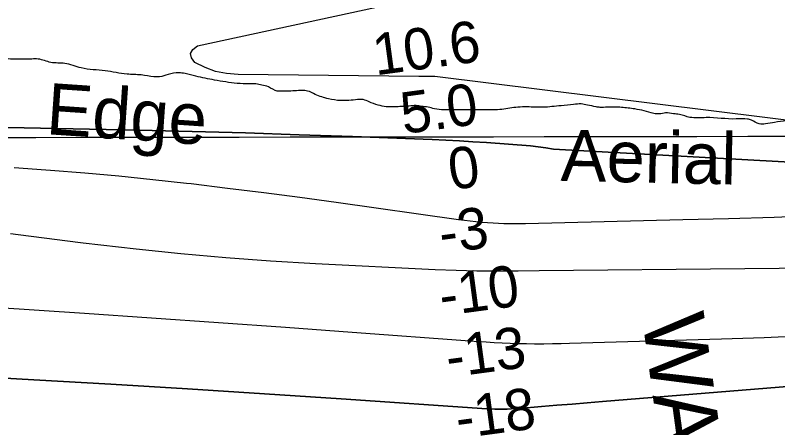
# Model space of a CAD drawing. Extents: x 3329297 to 3367176, y 649250 to 674653.
# Drawn here: x 3335278 to 3336510, y 660227 to 660894 of the extents above; entities that cross this region are included whole.
import ezdxf

# ---------------------------------------------------------------- set-up
doc = ezdxf.new("R2010")
doc.units = 0
for name, color, linetype in [('V-CHAN-NAID', 7, 'Continuous'), ('V-GRID-MAJR', 7, 'Continuous'), ('V-RIVR-EDGE', 7, 'Continuous'), ('V-RIVR-IDEN', 7, 'Continuous'), ('V-RIVR-RANG', 7, 'Continuous'), ('V-TOPO-DPTH', 7, 'Continuous'), ('V-TOPO-MINR', 7, 'Continuous'), ('V-TOPO-WATR', 7, 'Continuous')]:
    doc.layers.add(name, color=color, linetype=linetype)

msp = doc.modelspace()

# ---------------------------------------------------------------- linework, layer by layer
at = {"layer": 'V-GRID-MAJR'}
msp.add_spline([(3333421.13, 660693.428), (3338679.904, 660701.46), (3343938.678, 660710.256), (3349197.451, 660719.817), (3354456.222, 660730.142), (3359714.992, 660741.233), (3364973.7600000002, 660753.089), (3364973.761, 660753.089)], degree=3, dxfattribs=at)
at = {"layer": 'V-RIVR-EDGE'}
msp.add_spline([(3338937.398556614, 661038.9798826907), (3338922.836359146, 661016.6337518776), (3338913.2879107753, 661010.4401016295), (3338909.5534775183, 661008.7913995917), (3338900.440008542, 661010.8863548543), (3338872.2716634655, 661017.5877519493), (3338863.9820330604, 661017.6082498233), (3338847.3945731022, 661014.3333934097), (3338836.5955059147, 661005.2414472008), (3338822.87969468, 660989.9394524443), (3338803.3590923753, 660973.8228431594), (3338792.145543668, 660964.7319218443), (3338778.457404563, 660960.6209281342), (3338766.4374404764, 660960.6506500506), (3338750.670744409, 660954.0578916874), (3338739.877826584, 660947.4528346), (3338731.1439927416, 660935.4543932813), (3338722.8154163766, 660919.7245933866), (3338710.758556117, 660904.8329805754), (3338699.5429576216, 660894.91309622), (3338689.159396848, 660886.2346066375), (3338668.4199474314, 660880.0686285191), (3338645.5978414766, 660869.762959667), (3338618.61452202, 660852.8358354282), (3338593.279904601, 660832.1742779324), (3338577.0946274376, 660823.924618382), (3338559.2524490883, 660816.0935399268), (3338550.1348805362, 660816.5305691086), (3338538.9469541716, 660817.8016857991), (3338524.0461173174, 660826.1282123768), (3338507.906960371, 660836.5302212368), (3338499.6306535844, 660841.9389788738), (3338492.6111149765, 660852.7329215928), (3338476.8915640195, 660865.2063131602), (3338462.809441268, 660869.3859747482), (3338450.374995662, 660869.416721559), (3338418.4609434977, 660869.9101198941), (3338390.2649262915, 660865.4205159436), (3338365.786944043, 660855.9479097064), (3338351.2677921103, 660851.010002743), (3338337.587852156, 660850.2148611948), (3338306.0964806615, 660854.0230867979), (3338289.5213194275, 660855.7220086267), (3338264.2461458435, 660859.1003793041), (3338251.4013182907, 660860.79007709), (3338243.526169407, 660860.8095500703), (3338233.9879699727, 660858.7607150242), (3338222.78671999, 660854.6435719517), (3338211.5752210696, 660846.381613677), (3338201.1783366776, 660832.314864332), (3338189.927891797, 660808.3026082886), (3338183.261341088, 660794.2266349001), (3338178.666173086, 660779.7310555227), (3338170.7705263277, 660771.4608980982), (3338158.317632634, 660764.0309775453), (3338133.0158118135, 660756.632828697), (3338097.3509280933, 660748.8458206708), (3338043.0333510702, 660740.6904513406), (3337961.7744752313, 660732.6017001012), (3337939.4016971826, 660736.3873780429), (3337925.7412302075, 660743.4673853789), (3337919.956937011, 660750.9424012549), (3337915.424287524, 660761.7301946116), (3337898.1175281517, 660802.8069106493), (3337891.911579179, 660807.3815807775), (3337869.5377762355, 660810.7527771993), (3337845.49989785, 660811.6411840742), (3337821.0444632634, 660811.2871712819), (3337801.5587073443, 660809.2629336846), (3337782.0637273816, 660803.5083624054), (3337764.216424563, 660793.604876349), (3337739.713844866, 660774.1847136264), (3337721.0140064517, 660754.7502023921), (3337697.738473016, 660728.6952606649), (3337679.4746388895, 660717.963836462), (3337644.2119379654, 660705.2020252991), (3337603.984682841, 660696.182846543), (3337565.4245778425, 660690.8899018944), (3337510.301610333, 660692.2696573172), (3337469.272039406, 660694.0290478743), (3337430.314876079, 660695.7833139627), (3337388.874923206, 660699.2016554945), (3337358.619822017, 660700.105435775), (3337304.319668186, 660698.996252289), (3337262.866391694, 660697.026334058), (3337234.678573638, 660695.8525822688), (3337203.591434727, 660695.5149677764), (3337186.597692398, 660695.5569884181), (3337167.5233433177, 660692.2882813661), (3337153.831104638, 660686.5193615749), (3337137.251843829, 660686.5603573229), (3337124.4029167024, 660686.5921290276), (3337108.235062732, 660685.3886553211), (3337095.376911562, 660681.690093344), (3337086.671774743, 660681.2971345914), (3337075.483848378, 660682.568251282), (3337053.112095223, 660686.7684107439), (3337038.6083166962, 660688.0477265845), (3337026.9997594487, 660686.8329790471), (3337008.7625725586, 660686.87807437), (3337000.0574357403, 660686.4851156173), (3336990.1139788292, 660688.1676391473), (3336974.372905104, 660691.9369187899), (3336966.9173622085, 660694.0277744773), (3336960.7001394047, 660694.0431478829), (3336948.27184316, 660696.5607838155), (3336935.0053598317, 660695.350135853), (3336912.630531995, 660698.3068507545), (3336901.038373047, 660703.723807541), (3336890.6753101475, 660703.3349483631), (3336866.220900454, 660703.3954170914), (3336823.121996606, 660706.403376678), (3336801.991638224, 660709.7714984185), (3336787.48580991, 660710.2218512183), (3336751.422842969, 660709.0675724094), (3336727.3849645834, 660709.9559792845), (3336706.2556310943, 660713.7385825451), (3336691.7600517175, 660718.3337505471), (3336674.7652844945, 660717.9612896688), (3336645.3247978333, 660713.0602788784), (3336625.8451912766, 660713.5229304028), (3336606.791340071, 660718.5438537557), (3336592.2875615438, 660719.823169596), (3336570.7345224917, 660719.8764640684), (3336558.7135335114, 660719.4917044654), (3336550.4300524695, 660721.9990914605), (3336541.7310650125, 660724.0930218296), (3336533.855916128, 660724.1124948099), (3336524.320791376, 660723.3071043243), (3336504.8329856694, 660720.4539036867), (3336490.319983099, 660718.0028858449), (3336479.957945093, 660718.0285081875), (3336467.5388728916, 660724.2764778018), (3336461.3257496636, 660725.9497772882), (3336442.6740812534, 660725.9958975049), (3336394.1848678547, 660728.1882176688), (3336368.0735569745, 660728.667267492), (3336351.091088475, 660733.2685848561), (3336341.561088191, 660734.5356019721), (3336328.715235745, 660735.8108182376), (3336318.763579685, 660734.1774896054), (3336309.647036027, 660735.0290003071), (3336293.9069871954, 660739.2127614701), (3336278.992826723, 660742.1510282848), (3336257.4459370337, 660744.6912118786), (3336234.235996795, 660745.163087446), (3336223.043970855, 660744.7762780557), (3336216.4143163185, 660745.6216393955), (3336202.3291188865, 660748.557856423), (3336192.385661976, 660750.2403799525), (3336179.949166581, 660749.442163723), (3336160.0489291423, 660747.4189510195), (3336130.200110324, 660745.005854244), (3336105.332244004, 660745.4818293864), (3336089.995402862, 660745.1052689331), (3336064.288324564, 660741.4384786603), (3336035.687049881, 660740.6802332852), (3335999.6271576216, 660740.7693990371), (3335970.198969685, 660740.8421664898), (3335955.2817345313, 660742.5369887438), (3335944.925845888, 660745.0495002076), (3335934.1524010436, 660746.3195920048), (3335925.4513637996, 660747.584559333), (3335914.2583129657, 660746.7832684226), (3335899.3349284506, 660745.9912015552), (3335888.1429025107, 660745.604392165), (3335877.366382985, 660745.631039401), (3335864.110148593, 660748.5652066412), (3335849.6155941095, 660753.5748561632), (3335840.091743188, 660757.3287624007), (3335830.9731497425, 660757.351310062), (3335803.1987883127, 660755.7620518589), (3335783.725331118, 660758.7115925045), (3335762.6041967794, 660765.810047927), (3335750.183074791, 660771.2290545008), (3335741.4810126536, 660772.0795403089), (3335717.0235282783, 660770.8965644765), (3335708.319416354, 660770.9180872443), (3335701.27323051, 660770.935510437), (3335686.7838004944, 660778.0175675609), (3335676.4289367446, 660780.9445605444), (3335666.485479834, 660782.6270840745), (3335656.123441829, 660782.6527064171), (3335636.230378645, 660783.5308643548), (3335599.769328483, 660789.0093147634), (3335569.527550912, 660795.3013548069), (3335552.129575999, 660799.4892155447), (3335542.1850941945, 660800.7572575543), (3335524.769696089, 660797.8989324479), (3335511.0825818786, 660794.2024202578), (3335501.9639884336, 660794.2249679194), (3335481.2470866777, 660797.177583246), (3335458.453677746, 660798.47739696), (3335422.8215906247, 660803.9537975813), (3335384.2860830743, 660808.6084094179), (3335357.7766889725, 660815.7201884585), (3335335.3987864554, 660817.4334587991), (3335314.6880340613, 660822.8729632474), (3335304.7404775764, 660822.8975606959), (3335277.3836723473, 660822.5507221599), (3335247.549202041, 660825.940366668), (3335233.878486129, 660828.8755588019), (3335221.026484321, 660827.6638859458), (3335203.625434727, 660830.6083021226), (3335183.743645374, 660836.0457567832), (3335171.31534913, 660838.5633927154), (3335154.737113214, 660839.018869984), (3335125.2966265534, 660834.1178591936), (3335103.735388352, 660830.8553015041), (3335075.1402630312, 660832.5839452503), (3335059.384840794, 660830.5504836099), (3335036.1718258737, 660829.7789146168), (3335026.228368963, 660831.4614381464), (3335016.7004184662, 660833.5574183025), (3334988.130915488, 660845.6481000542), (3334968.2460514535, 660849.8421101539), (3334947.1064690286, 660849.4798982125), (3334935.092654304, 660851.9965092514), (3334919.773236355, 660858.6661346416), (3334910.6618171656, 660861.590052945), (3334896.5776446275, 660864.9407514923), (3334875.443186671, 660866.6509471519), (3334846.8429368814, 660866.3071832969), (3334814.088647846, 660862.243334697), (3334799.57667017, 660860.2067983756), (3334786.3122366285, 660859.8251134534), (3334763.9394585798, 660863.6107913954), (3334750.6760499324, 660863.6435879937), (3334729.9529988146, 660864.109314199), (3334716.282282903, 660867.0445063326), (3334687.694331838, 660871.6745207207), (3334669.46329431, 660874.2065051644), (3334645.8491214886, 660878.8242208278), (3334635.4901581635, 660880.0932877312), (3334625.5446514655, 660880.9468482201), (3334596.949526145, 660882.6754919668), (3334567.1037820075, 660881.5058397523), (3334557.5717319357, 660881.9438938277), (3334545.9723987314, 660884.4594799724), (3334521.960142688, 660895.7099248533), (3334508.2955761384, 660901.1320061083), (3334490.067613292, 660904.907435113), (3334462.7077333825, 660903.3171520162), (3334451.5157074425, 660902.9303426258), (3334433.69505186, 660903.8033760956), (3334404.697743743, 660910.5068229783), (3334381.0886953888, 660917.1969462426), (3334364.9331401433, 660920.9672507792), (3334352.917275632, 660922.6548987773), (3334336.75454613, 660923.5238326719), (3334316.437777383, 660920.6726818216), (3334296.5477888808, 660922.7942843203), (3334284.541148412, 660928.2122660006), (3334260.9239009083, 660931.5865371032), (3334243.938357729, 660934.9444099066), (3334228.60254148, 660934.9823309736), (3334209.532291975, 660933.3715500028), (3334195.436845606, 660932.162951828), (3334181.763055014, 660933.854699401), (3334171.4030667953, 660934.709284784), (3334166.848894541, 660936.7929662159), (3334153.5844610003, 660936.4112812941), (3334133.268717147, 660933.9746119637), (3334121.2549024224, 660936.4912230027), (3334114.214865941, 660938.9955353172), (3334098.0582858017, 660942.3513583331), (3334086.040371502, 660943.2100432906), (3334069.0538034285, 660946.1534345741), (3334054.956307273, 660944.1158733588), (3334034.2312063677, 660943.752636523), (3334004.815317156, 660948.7991822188), (3333961.735886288, 660959.6822906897), (3333930.2486143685, 660965.1484423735), (3333912.4402575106, 660970.995254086), (3333902.508074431, 660977.2370743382), (3333891.3344965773, 660984.3109323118), (3333867.3160911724, 660993.0744880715), (3333818.846350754, 661003.1419571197), (3333763.753105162, 661016.5416766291), (3333734.3484897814, 661026.147519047), (3333691.6855902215, 661037.8585656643), (3333658.539367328, 661042.914335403), (3333635.331476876, 661044.215174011), (3333621.6494871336, 661042.591069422), (3333588.8951980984, 661038.5272208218), (3333566.0946149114, 661036.9256638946), (3333542.057761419, 661038.2285522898), (3333498.9629571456, 661042.8944379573), (3333465.8218587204, 661050.0226152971), (3333420.687729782, 661060.1318435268)], degree=3, dxfattribs=at)
at = {"layer": 'V-TOPO-DPTH'}
for points in [[(3335026.822229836, 660717.3138612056), (3335477.2484609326, 660707.7378849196), (3335563.638599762, 660705.6865478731), (3335650.020286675, 660703.3491414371), (3335736.389295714, 660700.5826309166), (3335822.749852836, 660697.5300510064), (3335951.5333759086, 660692.6576272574), (3335973.4890870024, 660691.7065191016), (3335995.435807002, 660690.5952209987), (3336017.36904036, 660689.2436379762), (3336039.2932826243, 660687.7318650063), (3336110.386908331, 660682.438324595), (3336122.9389972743, 660681.174766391), (3336135.4211949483, 660679.4805481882), (3336147.7985557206, 660677.1403399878), (3336775.750459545, 660642.6610791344)], [(3336775.750459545, 660642.6610791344), (3336147.7985557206, 660677.1403399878), (3336135.4211949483, 660679.4805481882), (3336122.9389972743, 660681.174766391), (3336110.386908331, 660682.438324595), (3336039.2932826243, 660687.7318650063), (3336017.36904036, 660689.2436379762), (3335995.435807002, 660690.5952209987), (3335973.4890870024, 660691.7065191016), (3335951.5333759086, 660692.6576272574), (3335822.749852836, 660697.5300510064), (3335736.389295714, 660700.5826309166), (3335650.020286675, 660703.3491414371), (3335563.638599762, 660705.6865478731), (3335477.2484609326, 660707.7378849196), (3335026.822229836, 660717.3138612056)], [(3336788.996719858, 660486.9109705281), (3336124.140254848, 660480.7398634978), (3336090.6047070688, 660480.040770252), (3336057.069502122, 660479.8302104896), (3336023.541559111, 660480.0576026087), (3335990.024509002, 660480.9419225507), (3335956.514720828, 660482.2641943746), (3335762.9419088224, 660491.8030816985), (3335690.339409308, 660496.0912212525), (3335617.8141429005, 660501.3219623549), (3335545.404726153, 660507.9666057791), (3335473.072542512, 660515.5538507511), (3335387.3409469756, 660525.3931573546), (3335357.947108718, 660528.8822601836), (3335328.5726967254, 660532.523257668), (3335299.227424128, 660536.392097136), (3335269.901577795, 660540.4128312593)], [(3336788.996719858, 660486.9109705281), (3336124.140254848, 660480.7398634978), (3336090.6047070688, 660480.040770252), (3336057.069502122, 660479.8302104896), (3336023.541559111, 660480.0576026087), (3335990.024509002, 660480.9419225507), (3335956.514720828, 660482.2641943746), (3335762.9419088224, 660491.8030816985), (3335690.339409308, 660496.0912212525), (3335617.8141429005, 660501.3219623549), (3335545.404726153, 660507.9666057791), (3335473.072542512, 660515.5538507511), (3335387.3409469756, 660525.3931573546), (3335357.947108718, 660528.8822601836), (3335328.5726967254, 660532.523257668), (3335299.227424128, 660536.392097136), (3335269.901577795, 660540.4128312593)], [(3335027.216501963, 660320.3298959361), (3335307.8266306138, 660304.4769204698), (3335432.061754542, 660297.2399907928), (3335556.2787930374, 660289.7130139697), (3335680.4687033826, 660281.7509664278), (3335804.640528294, 660273.4988717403), (3336039.936951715, 660257.4477841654), (3336046.449087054, 660257.0894397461), (3336052.964000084, 660256.8452435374), (3336059.48307965, 660256.7722696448), (3336066.0049369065, 660256.8134439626), (3336072.5259047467, 660256.9999417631), (3336079.0429076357, 660257.2658121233), (3336085.553963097, 660257.6507413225), (3336092.061053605, 660258.1150430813), (3336128.2662914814, 660261.03121245), (3336152.872819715, 660263.0157110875), (3336177.4790743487, 660265.0035920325), (3336202.084918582, 660266.9965464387), (3336226.6904892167, 660268.9928831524), (3336638.2861008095, 660302.429799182)], [(3335027.216501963, 660320.3298959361), (3335307.8266306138, 660304.4769204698), (3335432.061754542, 660297.2399907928), (3335556.2787930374, 660289.7130139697), (3335680.4687033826, 660281.7509664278), (3335804.640528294, 660273.4988717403), (3336039.936951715, 660257.4477841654), (3336046.449087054, 660257.0894397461), (3336052.964000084, 660256.8452435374), (3336059.48307965, 660256.7722696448), (3336066.0049369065, 660256.8134439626), (3336072.5259047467, 660256.9999417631), (3336079.0429076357, 660257.2658121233), (3336085.553963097, 660257.6507413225), (3336092.061053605, 660258.1150430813), (3336128.2662914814, 660261.03121245), (3336152.872819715, 660263.0157110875), (3336177.4790743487, 660265.0035920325), (3336202.084918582, 660266.9965464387), (3336226.6904892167, 660268.9928831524), (3336638.2861008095, 660302.429799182)]]:
    msp.add_lwpolyline(points, dxfattribs=at)
at = {"layer": 'V-TOPO-MINR'}
for points in [[(3336671.246528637, 660705.507688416), (3335955.7519082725, 660794.5236306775), (3335929.6918719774, 660794.5995018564), (3335637.7593475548, 660797.9016626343), (3335619.4037258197, 660799.554512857), (3335601.55050476, 660803.0242795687), (3335584.4508847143, 660809.2194210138), (3335567.8536653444, 660817.2314789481), (3335562.4844368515, 660824.9696235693), (3335560.791281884, 660832.1257432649), (3335564.6122372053, 660838.4088255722), (3335572.109266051, 660844.1098829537), (3335948.6460161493, 660926.0144875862)], [(3336577.799186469, 660569.7245923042), (3336504.0892981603, 660566.9734813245), (3336430.363517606, 660564.6875399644), (3336356.627142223, 660562.7117116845), (3336102.5523413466, 660556.7057063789), (3336093.7583117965, 660556.5557107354), (3336084.9641507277, 660556.482859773), (3336076.1697923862, 660556.5257258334), (3336067.3753025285, 660556.6457365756), (3336058.586370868, 660556.9218965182), (3336049.804972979, 660557.328928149), (3336041.034875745, 660557.9322673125), (3336032.2723122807, 660558.6664781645), (3336031.2578682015, 660558.7629166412), (3336022.000949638, 660559.7050017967), (3336012.7536405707, 660560.7289036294), (3336003.520745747, 660561.8755304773), (3335994.2974604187, 660563.103974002), (3335796.122960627, 660590.8393846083), (3335737.7015437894, 660598.8165295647), (3335679.246578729, 660606.5328045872), (3335620.7412913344, 660613.8577747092), (3335562.202455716, 660620.9218748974), (3335554.707708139, 660621.8008642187), (3335499.8564157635, 660627.8643675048), (3335444.958919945, 660633.4408308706), (3335389.9921189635, 660638.2867343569), (3335334.979114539, 660642.6455979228), (3335327.2773639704, 660643.2043215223), (3335276.072527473, 660646.793501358)], [(3336788.996719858, 660486.9109705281), (3336124.140254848, 660480.7398634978), (3336090.6047070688, 660480.040770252), (3336057.069502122, 660479.8302104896), (3336023.541559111, 660480.0576026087), (3335990.024509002, 660480.9419225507), (3335956.514720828, 660482.2641943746), (3335762.9419088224, 660491.8030816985), (3335690.339409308, 660496.0912212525), (3335617.8141429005, 660501.3219623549), (3335545.404726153, 660507.9666057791), (3335473.072542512, 660515.5538507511), (3335387.3409469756, 660525.3931573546), (3335357.947108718, 660528.8822601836), (3335328.5726967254, 660532.523257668), (3335299.227424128, 660536.392097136), (3335269.901577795, 660540.4128312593)], [(3336556.6738866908, 660375.5839909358), (3336487.807860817, 660372.4030105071), (3336418.9054398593, 660369.9009645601), (3336173.5362204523, 660362.8079507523), (3336159.7400721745, 660362.479905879), (3336145.9428097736, 660362.246162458), (3336132.143876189, 660362.1538712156), (3336118.343828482, 660362.1558814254), (3336116.8284867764, 660362.163869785), (3336103.7875342, 660362.3169026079), (3336090.74959389, 660362.5822566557), (3336077.7161719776, 660363.0160925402), (3336064.6857623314, 660363.5622496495), (3336051.660739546, 660364.2435591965), (3336038.639885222, 660364.9926977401), (3336025.62528359, 660365.8435797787), (3336012.614850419, 660366.7622908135), (3335822.430457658, 660380.9390062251), (3335714.3210079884, 660388.8551550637), (3335606.19829599, 660396.582241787), (3335498.0556904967, 660404.0257353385), (3335389.899822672, 660411.280166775), (3335169.439005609, 660425.7769539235)], [(3336638.2861008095, 660302.429799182), (3336226.6904892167, 660268.9928831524), (3336202.084918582, 660266.9965464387), (3336177.4790743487, 660265.0035920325), (3336152.872819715, 660263.0157110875), (3336128.2662914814, 660261.03121245), (3336092.061053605, 660258.1150430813), (3336085.553963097, 660257.6507413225), (3336079.0429076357, 660257.2658121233), (3336072.5259047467, 660256.9999417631), (3336066.0049369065, 660256.8134439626), (3336059.48307965, 660256.7722696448), (3336052.964000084, 660256.8452435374), (3336046.449087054, 660257.0894397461), (3336039.936951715, 660257.4477841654), (3335804.640528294, 660273.4988717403), (3335680.4687033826, 660281.7509664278), (3335556.2787930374, 660289.7130139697), (3335432.061754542, 660297.2399907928), (3335307.8266306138, 660304.4769204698), (3335027.216501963, 660320.3298959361)]]:
    msp.add_lwpolyline(points, dxfattribs=at)
at = {"layer": 'V-TOPO-WATR'}
msp.add_lwpolyline([(3336775.750459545, 660642.6610791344), (3336147.7985557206, 660677.1403399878), (3336135.4211949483, 660679.4805481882), (3336122.9389972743, 660681.174766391), (3336110.386908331, 660682.438324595), (3336039.2932826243, 660687.7318650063), (3336017.36904036, 660689.2436379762), (3335995.435807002, 660690.5952209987), (3335973.4890870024, 660691.7065191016), (3335951.5333759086, 660692.6576272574), (3335822.749852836, 660697.5300510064), (3335736.389295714, 660700.5826309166), (3335650.020286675, 660703.3491414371), (3335563.638599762, 660705.6865478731), (3335477.2484609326, 660707.7378849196), (3335026.822229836, 660717.3138612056)], dxfattribs=at)

# ---------------------------------------------------------------- texts
at = {"layer": 'V-CHAN-NAID'}
msp.add_text('WADLINGTON "214" (214.0)', height=100.00000200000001, rotation=277.76282084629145, dxfattribs=at).set_placement((3336290.779292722, 660404.2198229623))
at = {"layer": 'V-RIVR-IDEN'}
for s, height, rotation, p in [('Edge', 83.00000000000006, 356.09950625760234, (3335326.30784592, 660701.5627440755)), ('Aerial ', 83, 358.7490817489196, (3336158.646237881, 660626.059958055))]:
    msp.add_text(s, height=height, rotation=rotation, dxfattribs=at).set_placement(p)
at = {"layer": 'V-RIVR-RANG'}
for s, height, p in [('10.6', 66.99999999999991, (3335859.994243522, 660796.3736899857)), ('5.0', 66.99999999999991, (3335905.008572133, 660701.5401693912)), ('0', 67, (3335982.1756418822, 660611.0423862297)), ('-3', 67, (3335966.8026761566, 660508.0642611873)), ('-10', 67, (3335967.115462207, 660407.2006178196)), ('-13', 67, (3335977.8837494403, 660307.7482955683)), ('-18', 67, (3335993.619874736, 660208.9658758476))]:
    msp.add_text(s, height=height, rotation=7.681416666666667, dxfattribs=at).set_placement(p)

doc.saveas('drawing.dxf')
